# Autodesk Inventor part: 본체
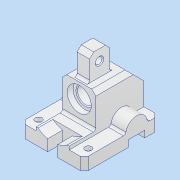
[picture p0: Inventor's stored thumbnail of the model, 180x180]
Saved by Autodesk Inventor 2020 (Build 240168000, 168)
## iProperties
Created: 2022-08
Part Number: 본체
Material: 알루미늄 6061
Document SubType Name: Modeling
Designer: user
Density: 2.7 g/cm^3
Appearance: 알루미늄 - 평지
Mass: 502.052 g
Surface Area: 340.317 cm^2
Volume: 185.945 cm^3
Author: user
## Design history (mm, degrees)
sketch "스케치1"
  geometry: L1 (-20, 18)-(20, 18); L2 (20, 18)-(20, -42); L3 (20, -42)-(-20, -42); L4 (-20, -42)-(-20, 18); 2 further points
  constraints: 8 end point, 2 parallel, 1 horizontal, 1 midpoint, 1 perpendicular, 1 vertical alignment
  dimensions: "d0" = 42 distance from line of point (0, 0) L3; "d1" = 60 distance of L3.end L1.start; "d2" = 40 distance of L1.start L1.end
extrude "돌출1" new body sketch "스케치1" distance "d3" = 90; taper "d4" = 0 deg
sketch "스케치2"
  geometry: L1 (-38, -27)-(38, -27); L2 (38, -27)-(38, -42); L3 (38, -42)-(-38, -42); L4 (-38, -42)-(-38, -27); L5 (-20, -42)-(20, -42) reference; 2 further points
  constraints: 8 end point, 2 midpoint, 2 parallel, 1 horizontal, 1 perpendicular
  dimensions: "d5" = 76 distance of L1.start L1.end; "d6" = 15 distance of L3.end L1.start
extrude "돌출2" join sketch "스케치2" distance "d7" = 90; taper "d8" = 0 deg
sketch "스케치3"
  geometry: L1 (-20, 18)-(20, 18); L2 (20, 18)-(20, -23); L3 (20, -23)-(-20, -23); L4 (-20, -23)-(-20, 18); L5 (-38, -42)-(38, -42) reference; 3 further points
  constraints: 8 end point, 2 coincident, 2 parallel, 1 horizontal, 1 perpendicular
  dimensions: "d9" = 19 distance between parallel lines of L5 L3
extrude "돌출3" cut sketch "스케치3" distance "d10" = 32; taper "d11" = 0 deg
sketch "스케치4"
  geometry: L1 (0, 15)-(-90, 15) reference; L2 (-90, 0)-(-90, 15) reference; C1 r 13 at (-63, 15); 1 further point
  constraints: 1 centre point, 1 point on line
  dimensions: "d12" = 26 diameter of C1; "d13" = 27 distance from line of L2 C1.centre
extrude "돌출4" join sketch "스케치4" distance "d14" = 76; taper "d15" = 0 deg
sketch "스케치5"
  geometry: L1 (48, 53)-(18, 53); L2 (18, 53)-(18, 29); L3 (18, 29)-(48, 29); L4 (48, 29)-(48, 53); L5 (18, 0)-(18, 58) reference; L6 (18, 0)-(-27, 0) reference; L7 (-23, 58)-(18, 58) reference; 2 further points
  constraints: 8 end point, 2 parallel, 1 horizontal, 1 midpoint, 1 perpendicular, 1 point on line
  dimensions: "d16" = 24 distance of L3.end L1.start; "d18" = 30 distance of L1.start L1.end; "d27" = 5 distance between parallel lines of L7 L1
extrude "돌출5" join sketch "스케치5" stored distance "d19" = 15; taper "d20" = 0 deg
sketch "스케치6"
  geometry: C1 r 29 at (0, 0); 1 further point
  constraints: 1 centre point, 1 coincident
  dimensions: "d21" = 58 diameter of C1
extrude "돌출6" cut sketch "스케치6" distance "d22" = 18; taper "d23" = 0 deg
sketch "스케치7"
  geometry: L1 (-6, -23)-(6, -23); L2 (6, -23)-(6, -42); L3 (6, -42)-(-6, -42); L4 (-6, -42)-(-6, -23); L5 (-38, -42)-(38, -42) reference; L6 (-17.664, -23)-(17.664, -23) reference; 3 further points
  constraints: 8 end point, 4 midpoint, 2 parallel, 1 horizontal, 1 perpendicular
  dimensions: "d24" = 12 distance of L1.start L1.end
extrude "돌출7" cut sketch "스케치7" distance "d25" = 18; taper "d26" = 0 deg
sketch "스케치8"
  geometry: L1 (-73, 8)-(-53, 8); L2 (-53, 8)-(-53, 0); L3 (-53, 0)-(-73, 0); L4 (-73, 0)-(-73, 8); L5 (0, 0)-(-90, 0) reference; L6 (-90, 0)-(-90, 15) reference; 2 further points
  constraints: 8 end point, 2 parallel, 1 horizontal, 1 midpoint, 1 perpendicular, 1 point on line
  dimensions: "d28" = 20 distance of L1.start L1.end; "d29" = 27 distance from line of L6 point (-63, 0); "d30" = 8 distance of L1.end L2.end
extrude "돌출8" cut sketch "스케치8" extent not by distance; stored distance "d31" = 0; taper "d32" = 0 deg
sketch "스케치9"
  geometry: C1 r 14.5 at (0, 0); 1 further point
  constraints: 1 centre point, 1 coincident
  dimensions: "d33" = 29 diameter of C1
extrude "돌출9" cut sketch "스케치9" distance "d34" = 7; taper "d35" = 0 deg
sketch "스케치10"
  geometry: C1 r 10 at (0, 0); 1 further point
  constraints: 1 centre point, 1 coincident
  dimensions: "d36" = 20 diameter of C1
extrude "돌출10" cut sketch "스케치10" extent not by distance; stored distance "d37" = 0; taper "d38" = 0 deg
sketch "스케치11"
  geometry: L1 (-29, 18)-(-29, 48) reference; C1 r 4 at (-41, 35); 1 further point
  constraints: 1 centre point
  dimensions: "d39" = 8 diameter of C1; "d40" = 35 vertical distance of C1.centre point (0, 0); "d41" = 12 distance from line of C1.centre L1
extrude "돌출11" cut sketch "스케치11" extent not by distance; stored distance "d42" = 0; taper "d43" = 0 deg
sketch "스케치12"
  geometry: L1 (18, 0)-(0, 0) reference; 3 further points
  constraints: 1 horizontal alignment
  dimensions: "d44" = 60 distance of point (68, 13) point (8, 13); "d45" = 30 horizontal distance of point (8, 13) point (38, 90); "d46" = 13 distance from line of L1 point (8, 13)
hole "구멍1" sketch "스케치12" at (8, 13), (68, 13) diameter "d47" = 4.5; stored, may be unused: countersink angle "d51" = 90 deg, drill point angle "d53" = 0 deg; dims "d48" = 16, "d49" = 8, "d50" = 4.4, "d52" = 8
chamfer "모따기1" distance "d54" = 18; stored, may be unused: second distance "d55" = 2, angle "d56" = 45 deg
chamfer "모따기2" distance "d57" = 5; stored, may be unused: second distance "d58" = 2, angle "d59" = 45 deg
chamfer "모따기3" distance "d60" = 1; stored, may be unused: second distance "d61" = 2, angle "d62" = 45 deg
fillet "모깎기1" dims "d63" = 3
node "작업 평면1"
sketch "스케치13"
  geometry: L1 (-72, 45)-(-32, 45) reference; L2 (-32, 7)-(-32, 45) reference; 2 further points
  constraints: 1 other
  dimensions: "d65" = 18 distance from line of L1 point (-58, 27); "d66" = 26 distance from line of L2 point (-58, 27)
feature "엠보싱1" sketch "스케치13" dims "d0" = 42, "d1" = 60, "d2" = 40, "d6" = 15, "d67" = 0.5, "d68" = 0
chamfer "모따기4" distance "d69" = 5; stored, may be unused: second distance "d70" = 2, angle "d71" = 45 deg
node "솔리드1"
feature "A9D066F2-1C7D-4E18-AEED-F7BC21143FA4" dims "d47" = 4.5, "d48" = 16, "d49" = 8, "d50" = 4.4, "d51" = 90 deg, "d52" = 8, "d53" = 0
other parameters: "d64" = 36.25
